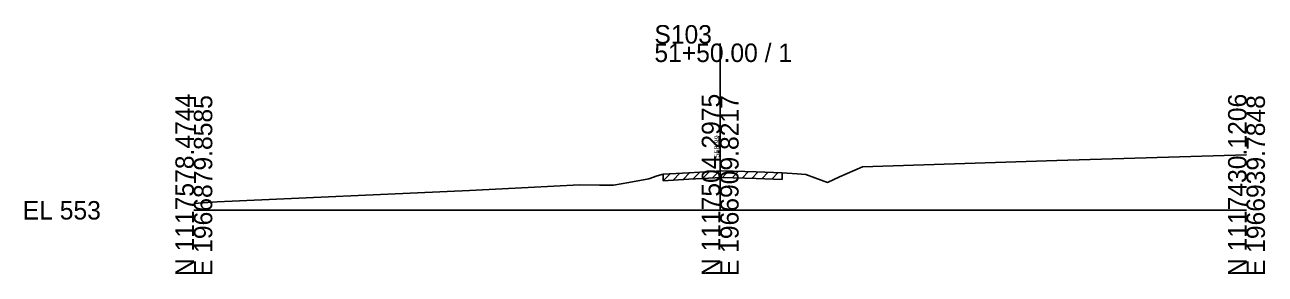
# Model space of a CAD drawing. Extents: x -26 to 163, y -10 to 24018.
# Drawn here: x -25.7 to 162.8, y 990.3 to 1028.2 of the extents above; entities that cross this region are included whole.
import ezdxf

# ---------------------------------------------------------------- set-up
doc = ezdxf.new("R2010")
doc.units = 0
for name, color, linetype in [('RD_GPK_XS_Cell', 7, 'Continuous'), ('RD_XS_ExGround', 7, 'Continuous'), ('RD_XS_ExPaveRet', 7, 'Continuous'), ('RD_XS_TX_Elev_EX', 7, 'Continuous')]:
    doc.layers.add(name, color=color, linetype=linetype)

msp = doc.modelspace()

# ---------------------------------------------------------------- linework, layer by layer
at = {"layer": 'RD_GPK_XS_Cell'}
for p, q in [((80, 1000), (80, 1025.31)), ((0, 1000), (80, 1000)), ((80, 1000), (160, 1000))]:
    msp.add_line(p, q, dxfattribs=at)
at = {"layer": 'RD_XS_ExGround'}
msp.add_lwpolyline([(0, 1001.05), (3.54, 1001.28), (41.89, 1003.03), (50.81, 1003.45), (58.64, 1003.89), (61.68, 1003.82), (63.78, 1003.8), (66.1, 1004.21), (69.16, 1004.76), (70.41, 1005.21), (71.33, 1005.47), (75.26, 1005.71), (80.27, 1006), (85.47, 1005.83), (89.42, 1005.7), (91.69, 1005.53), (93.04, 1005.43), (94.39, 1004.95), (96.33, 1004.24), (98.16, 1005.08), (101.61, 1006.62), (131.18, 1007.54), (160, 1008.44)], dxfattribs=at)
at = {"layer": 'RD_XS_ExPaveRet'}
for p, q in [((71.33, 1004.47), (72.39, 1005.53)), ((71.33, 1004.47), (71.33, 1005.47)), ((72.83, 1004.56), (73.89, 1005.63)), ((74.33, 1004.65), (75.39, 1005.72)), ((75.26, 1004.71), (80.27, 1005)), ((75.83, 1004.74), (76.89, 1005.81)), ((77.33, 1004.83), (78.39, 1005.89)), ((78.83, 1004.92), (79.89, 1005.98)), ((80.27, 1005), (85.47, 1004.83)), ((80.33, 1005), (81.29, 1005.97)), ((81.83, 1004.95), (82.79, 1005.92)), ((83.33, 1004.9), (84.29, 1005.87)), ((84.83, 1004.85), (85.79, 1005.82)), ((86.33, 1004.8), (87.3, 1005.77)), ((87.83, 1004.75), (88.8, 1005.72)), ((89.42, 1005.7), (89.42, 1004.7)), ((71.33, 1004.47), (75.26, 1004.71)), ((85.47, 1004.83), (89.42, 1004.7))]:
    msp.add_line(p, q, dxfattribs=at)

# ---------------------------------------------------------------- texts
at = {"layer": 'RD_GPK_XS_Cell'}
for s, p in [('S103', (70, 1025.31)), ('51+50.00 / 1', (70, 1022.51)), ('EL 553', (-26, 998.6))]:
    msp.add_text(s, height=2.8, dxfattribs=at).set_placement(p)
for s, p in [('N 1117578.4744', (0, 990)), ('E 1966879.8585', (2.8, 990)), ('N 1117504.2975', (80, 990)), ('E 1966909.8217', (82.8, 990)), ('N 1117430.1206', (160, 990)), ('E 1966939.7848', (162.8, 990))]:
    msp.add_text(s, height=2.8, rotation=90, dxfattribs=at).set_placement(p)
at = {"layer": 'RD_XS_TX_Elev_EX'}
msp.add_text('558.99', height=0.8, rotation=90, dxfattribs=at).set_placement((79.9, 1007.99))

doc.saveas('drawing.dxf')
